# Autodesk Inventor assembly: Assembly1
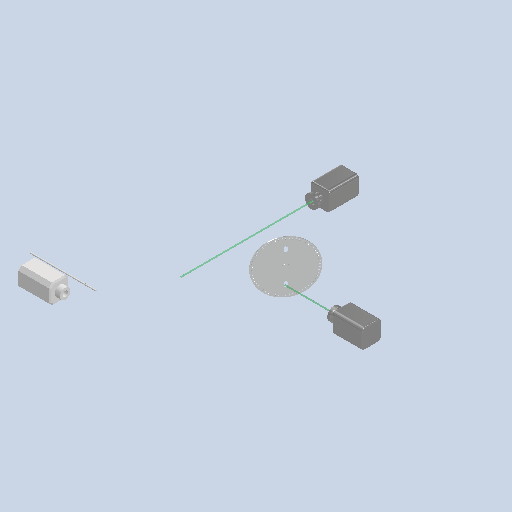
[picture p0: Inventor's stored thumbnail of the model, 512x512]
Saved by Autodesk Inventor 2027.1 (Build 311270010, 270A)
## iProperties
Created: 2026-07
Part Number: Assembly1
Document SubType Name: Assembly
Designer: dunge
Author: dunge
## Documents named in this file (7)
- C:\Users\dunge\OneDrive\Documents\Inventor\Inventor\Inventor\simplified-drawings\figure-1c.iam
- C:\Users\dunge\OneDrive\Documents\Inventor\Inventor\Inventor\simplified-drawings\chopper-simple.ipt
- C:\Users\dunge\OneDrive\Documents\Inventor\Inventor\Inventor\simplified-drawings\generic-beam.ipt
- C:\Users\dunge\OneDrive\Documents\Inventor\Inventor\Inventor\simplified-drawings\emitter-simple.ipt
- C:\Users\dunge\OneDrive\Documents\Inventor\Inventor\Inventor\simplified-drawings\collector-simple.ipt
- C:\Users\dunge\OneDrive\Documents\Inventor\Inventor\Inventor\simplified-drawings\generic-beam-shorter.ipt
- C:\Users\dunge\OneDrive\Documents\Inventor\Inventor\Inventor\simplified-drawings\plane.ipt
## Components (8 placed, 6 different names)
1. chopper-simple:1 — Tangent:1
2. generic-beam:1 — Mate:6, Rigid:1
3. emitter-simple:1
4. collector-simple:1 — Mate:5, Mate:6, Rigid:1
5. collector-simple:2 — Mate:3, Flush:1, Flush:2, Mate:4, Angle:1
6. generic-beam-shorter:1 — Mate:4, Angle:1
7. plane:1 — Mate:3, Flush:1, Flush:2, Tangent:1, Mate:5
8. generic-beam-shorter:2
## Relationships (9: Mate 4, Flush 2, Angle 1, Tangent 1, WeldJoint 1)
- Mate:3: collector-simple:2 ↔ plane:1
- Flush:1: collector-simple:2 ↔ plane:1
- Flush:2: collector-simple:2 ↔ plane:1
- Mate:4: collector-simple:2 ↔ generic-beam-shorter:1
- Angle:1: collector-simple:2 ↔ generic-beam-shorter:1
- Tangent:1: chopper-simple:1 ↔ plane:1
- Mate:5: collector-simple:1 ↔ plane:1
- Mate:6: generic-beam:1 ↔ collector-simple:1
- Rigid:1 [WeldJoint]: generic-beam:1 ↔ collector-simple:1
## Named parameters: Finish4_Area = 82.84667 mm, Finish5_Area = 662.56225 mm, Finish6_Area = 421.26303 mm
